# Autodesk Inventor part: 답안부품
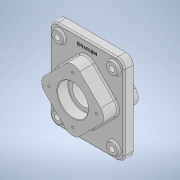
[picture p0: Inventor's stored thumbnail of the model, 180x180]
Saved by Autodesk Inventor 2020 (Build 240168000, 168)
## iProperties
Created: 2021-07
Part Number: 답안부품
Material: 일반
Document SubType Name: Modeling
Designer: Owner
Density: 1 g/cm^3
Appearance: 기본값
Mass: 807.977 g
Surface Area: 961.758 cm^2
Volume: 807.977 cm^3
Author: Owner
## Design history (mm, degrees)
sketch "스케치1"
  geometry: L1 (-75, -90)-(75, -90); L2 (75, -90)-(75, 90); L3 (75, 90)-(-75, 90); L4 (-75, 90)-(-75, -90); L5 (-75, -90)-(75, 90); L6 (75, -90)-(-75, 90); 1 further point
  constraints: 12 end point, 2 midpoint, 2 parallel, 1 horizontal, 1 perpendicular
  dimensions: "d0" = 150 distance of L3.end L2.end; "d1" = 180 distance of L2.end L1.end
extrude "돌출1" new body sketch "스케치1" stored distance "d2" = 18; taper "d3" = 0 deg
sketch "스케치2"
  geometry: L1 (-70.711, 0)-(0, 70.711); L2 (0, 70.711)-(70.711, 0); L3 (70.711, 0)-(0, -70.711); L4 (0, -70.711)-(-70.711, 0); L5 (-70.711, 0)-(70.711, 0); L6 (0, 70.711)-(0, -70.711); 2 further points
  constraints: 12 end point, 3 midpoint, 2 parallel, 1 perpendicular, 1 vertical alignment
  dimensions: "d4" = 100 distance of L1.end L2.end; "d5" = 100 distance of L1.start L1.end
extrude "돌출2" join sketch "스케치2" distance "d6" = 38; taper "d7" = 0 deg; dims "d25" = 32, "d26" = 0
fillet "모깎기1" dims "d8" = 20
fillet "모깎기2" dims "d9" = 3
fillet "모깎기3" dims "d10" = 15
fillet "모깎기4" dims "d27" = 3
sketch "스케치5"
  geometry: C1 r 31 at (0, 0); 1 further point
  constraints: 1 centre point, 1 coincident
  dimensions: "d28" = 62 diameter of C1
hole "구멍3" sketch "스케치5" at (0, 0) diameter "d29" = 45; stored, may be unused: countersink angle "d33" = 90 deg, drill point angle "d35" = 118 deg; dims "d30" = 6, "d31" = 62, "d32" = 22, "d34" = 8
sketch "스케치6"
  geometry: C1 r 22.5 at (0, 0) reference; 2 further points
  constraints: 1 coincident
hole "구멍4" sketch "스케치6" at (0, 0) diameter "d36" = 45; stored, may be unused: countersink angle "d40" = 90 deg, drill point angle "d42" = 118 deg; dims "d37" = 6, "d38" = 62, "d39" = 22, "d41" = 8
fillet "모깎기5" dims "d50" = 1
sketch "스케치8"
  geometry: L1 (75, -75)-(75, 75) reference; L2 (-75, 75)-(-75, -75) reference; C1 r 11 at (-55, 70); C2 r 11 at (55, 70); 1 further point
  constraints: 2 centre point, 1 horizontal alignment
  dimensions: "d51" = 22 diameter of C1; "d52" = 22 diameter of C2; "d53" = 110 distance of C2.centre C1.centre; "d54" = 55 horizontal distance of point (0, 0) C1.centre; "d55" = 70 vertical distance of point (0, 0) C1.centre; "d95" = 55 horizontal distance of point (0, 0) C2.centre (derived); "d96" = 150 distance between parallel lines of L1 L2 (derived); "d97" = 70 vertical distance of C2.centre point (0, 0) (derived)
extrude "돌출3" join sketch "스케치8" distance "d56" = 5; taper "d57" = 0 deg
sketch "스케치9"
  geometry: C1 r 11 at (0, 0) reference; 2 further points
  constraints: 1 coincident
hole "구멍6" sketch "스케치9" at (0, 0) diameter "d58" = 11; stored, may be unused: countersink angle "d62" = 90 deg, drill point angle "d64" = 118 deg; dims "d59" = 12, "d60" = 62, "d61" = 22, "d63" = 17.1
fillet "모깎기6" dims "d65" = 3
sketch "스케치10" dims "d66" = 96
  geometry: C1 r 22.5 at (0, 0) reference; 3 further points
  constraints: 1 coincident, 1 vertical alignment, 2 other
hole "구멍7" sketch "스케치10" at (0, 48) diameter "d67" = 4.917; stored, may be unused: countersink angle "d71" = 90 deg, drill point angle "d73" = 118 deg; dims "d68" = 10, "d69" = 62, "d70" = 22, "d72" = 13
sketch "스케치11" dims "d78" = 96
  geometry: C1 r 22.5 at (0, 0) reference; 3 further points
  constraints: 1 coincident, 1 vertical alignment, 2 other
hole "구멍8" sketch "스케치11" at (0, 48) diameter "d79" = 4.917; stored, may be unused: countersink angle "d83" = 90 deg, drill point angle "d85" = 118 deg; dims "d80" = 10, "d81" = 62, "d82" = 22, "d84" = 13
sketch "스케치12"
  geometry: L1 (60, 90)-(-60, 90) reference; 2 further points
  constraints: 1 vertical alignment, 1 other
  dimensions: "d89" = 15 distance from line of point (0, 75) L1
feature "엠보싱1" sketch "스케치12" dims "d0" = 150, "d1" = 180, "d9" = 3, "d90" = 0.5, "d91" = 0
chamfer "모따기1" distance "d92" = 1; stored, may be unused: second distance "d93" = 2, angle "d94" = 45 deg
node "솔리드1"
mirror "미러4"
mirror "미러5"
pattern_circular "원형 패턴1" dims angle "d75" = 360 deg
pattern_circular "원형 패턴2" dims angle "d87" = 360 deg
feature "A9D066F2-1C7D-4E18-AEED-F7BC21143FA4" dims "d29" = 45, "d30" = 6, "d31" = 62, "d32" = 22, "d33" = 90 deg, "d34" = 8, "d35" = 118 deg
